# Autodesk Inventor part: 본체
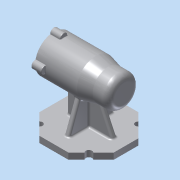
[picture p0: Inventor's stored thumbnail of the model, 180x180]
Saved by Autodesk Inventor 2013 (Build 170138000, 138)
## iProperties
Created: 2019-12
Part Number: 본체
Material: 알루미늄 6061
Document SubType Name: Modeling
Designer: Administrator
Density: 2.71 g/cm^3
Mass: 734.419 g
Surface Area: 723.811 cm^2
Volume: 271.003 cm^3
Author: Administrator
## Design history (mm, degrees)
sketch "스케치1"
  geometry: L1 (-56, 0)-(56, 0); L2 (-56, 0)-(-56, 25); L3 (-56, 25)-(-31, 25); L4 (-31, 25)-(-11, 30); L5 (-11, 30)-(56, 30); L6 (56, 0)-(56, 30); L7 (-47, 16)-(-43, 16); L8 (-43, 16)-(-43, 17.5); L9 (-43, 17.5)-(-25, 17.5); L10 (-25, 17.5)-(-25, 21); L11 (-25, 21)-(-13, 21); L12 (-13, 21)-(-13, 24); L13 (-13, 24)-(41, 24); L14 (41, 24)-(41, 21); L15 (41, 21)-(56, 21); L16 (-47, 16)-(-47, 10.5); L17 (-47, 10.5)-(-50, 10.5); L18 (-50, 10.5)-(-50, 0); 2 further points
  constraints: 36 end point, 11 perpendicular, 2 horizontal, 2 parallel, 2 point on line, 1 coincident, 1 midpoint
  dimensions: "d7" = 112 distance of L1.start L1.end; "d10" = 25 distance of L2.end L3.end; "d11" = 45 horizontal distance of L4.end L2.end; "d13" = 60 diameter of L5 L1; "d14" = 50 diameter of L3 L1; "d16" = 32 diameter of L7 L1; "d17" = 35 diameter of L9 L1; "d18" = 4 distance of L7.start L7.end; "d19" = 18 distance of L8.end L9.end; "d20" = 12 distance of L10.end L11.end; "d21" = 42 diameter of L11 L1; "d22" = 54 distance of L12.end L13.end; "d23" = 48 diameter of L13 L1; "d24" = 42 diameter of L15 L1; "d25" = 15 distance of L14.end L15.end; "d26" = 21 diameter of L17 L1; "d27" = 3 distance from line of L16.end L18
revolve "회전1" sketch "스케치1" stored, may be unused: angle "d28" = 90 deg
node "작업 평면1"
sketch "스케치2"
  geometry: L1 (-23.196, 56)-(23.196, 56); L2 (23.196, 56)-(59.473, 19.723); L3 (59.473, 19.723)-(59.473, -19.723); L4 (59.473, -19.723)-(23.196, -56); L5 (23.196, -56)-(-23.196, -56); L6 (-23.196, -56)-(-56, -23.196); L7 (-56, -23.196)-(-56, 23.196); L8 (-56, 23.196)-(-23.196, 56); C1 r 56 at (0, 0); 2 further points
  constraints: 16 end point, 4 tangent, 3 perpendicular, 3 vertical alignment, 1 centre point, 1 coincident, 1 horizontal, 1 midpoint, 1 vertical
  dimensions: "d32" = 56 distance from line of point (0, 0) L1; "d33" = 112 diameter of C1; "d35" = 56 distance from line of point (0, 0) L5; "d36" = 56 distance from line of point (0, 0) L7
extrude "돌출1" join sketch "스케치2" distance "d42" = 10; taper "d43" = 0 deg
sketch "스케치3"
  geometry: L1 (23.196, -56)-(56, -23.196) reference; L2 (56, -23.196)-(56, 23.196) reference; L3 (56, 23.196)-(23.196, 56) reference; L4 (-23.196, 56)-(-59.473, 19.723) reference; L5 (-59.473, -19.723)-(-23.196, -56) reference; C1 r 5 at (-39.598, 39.598); C2 r 5 at (39.598, 39.598); C3 r 5 at (39.598, -39.598); C4 r 5 at (-39.598, -39.598); A1 r 56 centre (0, 0) between (-39.598, 39.598) and (39.598, 39.598); 1 further point
  constraints: 5 centre point, 4 point on circle, 3 equal radius, 2 midpoint, 2 point on line, 1 coincident, 1 tangent
  dimensions: "d44" = 10 diameter of C1
extrude "돌출2" cut sketch "스케치3" distance "d46" = 10; taper "d47" = 0 deg
sketch "스케치4"
  geometry: C1 r 30 at (0, 0) reference; C2 r 21 at (0, 0)
  constraints: 1 centre point, 1 coincident
  dimensions: "d48" = 42 diameter of C2
extrude "돌출3" cut sketch "스케치4" distance "d50" = 15; taper "d51" = 0 deg
sketch "스케치5"
  geometry: C1 r 21 at (0, 0) reference; C2 r 24 at (0, 0)
  constraints: 1 centre point, 1 coincident
  dimensions: "d52" = 48 diameter of C2
extrude "돌출4" cut sketch "스케치5" distance "d54" = 54; taper "d55" = 0 deg
sketch "스케치6"
  geometry: C1 r 24 at (0, 0) reference; C2 r 21 at (0, 0)
  constraints: 1 centre point, 1 coincident
  dimensions: "d56" = 42 diameter of C2
extrude "돌출5" cut sketch "스케치6" distance "d58" = 12; taper "d59" = 0 deg
sketch "스케치7"
  geometry: C1 r 21 at (0, 0) reference; C2 r 17.5 at (0, 0)
  constraints: 1 centre point, 1 coincident
  dimensions: "d60" = 35 diameter of C2
extrude "돌출6" cut sketch "스케치7" distance "d62" = 18; taper "d63" = 0 deg
sketch "스케치8"
  geometry: C1 r 17.5 at (0, 0) reference; C2 r 16 at (0, 0)
  constraints: 1 centre point, 1 coincident
  dimensions: "d64" = 32 diameter of C2
extrude "돌출7" cut sketch "스케치8" distance "d66" = 4; taper "d67" = 0 deg
sketch "스케치9"
  geometry: C1 r 16 at (0, 0) reference; C2 r 10.5 at (0, 0)
  constraints: 1 centre point, 1 coincident
  dimensions: "d68" = 21 diameter of C2
extrude "돌출8" cut sketch "스케치9" distance "d70" = 3; taper "d71" = 0 deg
sketch "스케치10"
  geometry: L1 (-56, -25)-(-31, -25) reference; L2 (-11, -30)-(56, -30) reference; L3 (-23.196, -70)-(23.196, -70) reference; L4 (-36.062, -70)-(-23.196, -70) reference; L5 (-59.473, -70)-(-43.134, -70) reference; L6 (-43.134, -70)-(-34.598, -70) reference; L7 (-41.473, -70)-(-21.587, -27.353); L8 (23.196, -70)-(36.062, -70) reference; L9 (34.598, -70)-(43.134, -70) reference; L10 (43.134, -70)-(43.134, -80) reference; L11 (56, -80)-(43.134, -80) reference; L12 (56, -80)-(56, -70) reference; L13 (43.134, -70)-(56, -70) reference; L14 (43.134, -70)-(56, -70) reference; L15 (31, -30)-(31, -70); L16 (-41.473, -70)-(31, -70); L17 (-21.587, -27.353)-(-20.425, -24.861); L18 (-20.425, -24.861)-(31, -24.861); L19 (31, -24.861)-(31, -30); 1 further point
  constraints: 12 end point, 3 point on line, 2 perpendicular, 1 collinear, 1 parallel, 1 vertical
  dimensions: "d72" = 25 distance of L12.end L15.end; "d73" = 18 distance of L5.start L7.start; "d74" = 115 deg angle of L5 L7
extrude "돌출9" join sketch "스케치10" stored distance "d75" = 8; taper "d76" = 0 deg
sketch "스케치11"
  geometry: L1 (-70, 36.062)-(-70, 23.196) reference; L2 (-70, 43.134)-(-70, 34.598) reference; L3 (-70, 56)-(-70, 43.134) reference; L4 (-70, 23.196)-(-70, -23.196) reference; L5 (-70, -23.196)-(-70, -36.062) reference; L6 (-70, -34.598)-(-70, -43.134) reference; L7 (-70, -43.134)-(-70, -56) reference; L8 (-23.234, 18.979)-(-70, 36); L9 (-23.234, -18.979)-(-70, -36); A1 r 30 centre (0, 0) between (-23.234, 18.979) and (-23.234, -18.979) reference; 1 further point
  constraints: 4 end point, 2 point on circle, 2 point on line
  dimensions: "d77" = 20 distance of L3.start L8.end; "d78" = 20 distance of L7.end L9.end; "d79" = 110 deg angle of L3 L8; "d80" = 110 deg angle of L7 L9
feature "리브1" sketch "스케치11" dims "d81" = 1, "d82" = 8, "d83" = 0, "d84" = 0, "d85" = 1, "d86" = 1
sketch "스케치12"
  geometry: L1 (-70, 23.196)-(-70, -23.196) reference; L2 (-70, -23.196)-(-70, -36.062) reference; L3 (-70, -34.598)-(-70, -43.134) reference; L4 (-70, -43.134)-(-70, -56) reference; L5 (-23.234, -18.979)-(-70, -36); 2 further points
  constraints: 2 end point, 1 point on line, 2 other
  dimensions: "d87" = 20 distance of L4.end L5.end; "d88" = 110 deg angle of L4 L5
feature "리브2" sketch "스케치12" dims "d89" = 1, "d90" = 8, "d91" = 0, "d92" = 0, "d93" = 1, "d94" = 1
sketch "스케치13"
  geometry: C1 r 21 at (0, 0) reference; C2 r 30 at (0, 0); C3 r 6 at (0, 30); C4 r 6 at (-30, 0); C5 r 6 at (0, -30); C6 r 6 at (30, 0); A1 r 30 centre (0, 0) between (0, 30) and (30, 0) reference
  constraints: 5 centre point, 4 point on circle, 3 equal radius, 2 horizontal alignment, 2 vertical alignment, 1 coincident
  dimensions: "d95" = 60 diameter of C2; "d97" = 12 diameter of C3
extrude "돌출10" join sketch "스케치13" distance "d98" = 16; taper "d99" = 0 deg
sketch "스케치14"
  geometry: A1 r 6 centre (30, 30) between (35.97, 29.4) and (24.03, 29.4) reference; A2 r 6 centre (0, 0) between (0.6, 5.97) and (0.6, -5.97) reference; A3 r 6 centre (30, -30) between (24.03, -29.4) and (35.97, -29.4) reference; A4 r 6 centre (60, 0) between (59.4, -5.97) and (59.4, 5.97) reference; 4 further points
  constraints: 4 coincident
hole "구멍1" sketch "스케치14" at (30, 30), (0, 0), (30, -30), (60, 0) diameter "d100" = 3.242; stored, may be unused: countersink angle "d104" = 90 deg, drill point angle "d106" = 118 deg; dims "d101" = 8, "d102" = 4, "d103" = 2, "d105" = 11
fillet "모깎기1" dims "d107" = 1
fillet "모깎기2" dims "d108" = 1
fillet "모깎기3" dims "d109" = 1
fillet "모깎기4" dims "d110" = 1
fillet "모깎기5" dims "d111" = 3
fillet "모깎기6" dims "d112" = 3
fillet "모깎기7" dims "d113" = 3
fillet "모깎기8" dims "d114" = 3
fillet "모깎기9" dims "d115" = 3
fillet "모깎기10" dims "d116" = 3
fillet "모깎기11" dims "d117" = 3
fillet "모깎기12" dims "d118" = 10
fillet "모깎기13" dims "d119" = 3
chamfer "모따기1" distance "d120" = 1; stored, may be unused: second distance "d121" = 2, angle "d122" = 45 deg
fillet "모깎기14" dims "d123" = 3
fillet "모깎기15" dims "d124" = 3
fillet "모깎기16" dims "d125" = 0.3
fillet "모깎기17" dims "d126" = 0.3
node "작업 평면2"
sketch "스케치15"
  geometry: L1 (56, 6.771)-(56, 29.226) reference; L2 (56, 5.998)-(56, -5.998) reference; 3 further points
  constraints: 1 horizontal alignment, 1 midpoint, 1 other
  dimensions: "d128" = 41 distance from line of L1 point (15, 0)
feature "엠보싱1" sketch "스케치15" dims "d129" = 0.5, "d130" = 0
fillet "모깎기18" dims "d131" = 3
fillet "모깎기19" dims "d132" = 3
node "솔리드1"
node "투영된 루프1"
